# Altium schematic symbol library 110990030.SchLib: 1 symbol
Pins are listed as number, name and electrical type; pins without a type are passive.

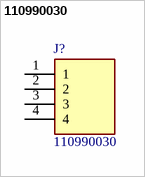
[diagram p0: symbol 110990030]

## 110990030
designator J?
GROVE 2MM 4PIN VERT CONN 10PCS; Manufacturer_Name: Seeed Studio; Geometry.Height: 8.6mm
footprint 110990030
pins: 1, 2, 3, 4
